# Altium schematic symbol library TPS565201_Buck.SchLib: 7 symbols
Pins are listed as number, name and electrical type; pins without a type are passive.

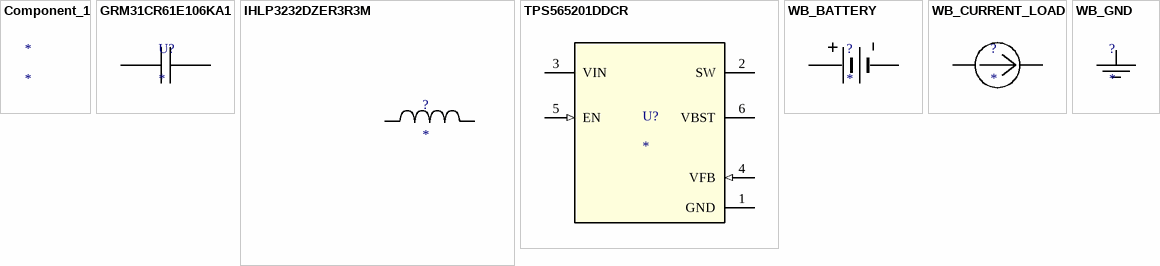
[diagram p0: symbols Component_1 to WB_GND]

## Component_1
designator *

## GRM31CR61E106KA1
designator U?
Imported; Manufacturer_Part_Number: GRM31CR61E106KA12L; Manufacturer_Name: MuRata; Cap_F: 0.00001; ESR_ohm: 0.004; VDC_V: 25; TYPE_2: TYPE
footprint 1206_190
pins: 1, 2

## IHLP3232DZER3R3M
designator ?
Imported; Manufacturer_Part_Number: IHLP3232DZER3R3M01; Manufacturer: Vishay; Vendor: Vishay-Dale; DESCRIPTION: Unknown; PACKAGE_DESIGNATOR: IHLP-3232DZ
footprint IHLP-3232DZ
pins: 1, 2

## TPS565201DDCR
designator U?
Imported; PartNumber: TPS565201DDCR; Manufacturer: Texas Instruments
footprint DDC0006A_N
pins: 1 GND (power), 2 SW (power), 3 VIN (power), 4 VFB (in), 5 EN (in), 6 VBST (power)

## WB_BATTERY
designator ?
Imported; Manufacturer_Part_Number: WB_BATTERY; PowerPortType: POWER_GROUND
pins: 1 +, 2 -

## WB_CURRENT_LOAD
designator ?
Imported; Manufacturer_Part_Number: WB_CURRENT_LOAD; PowerPortType: POWER_GROUND
pins: 1 +, 2 -

## WB_GND
designator ?
Imported; Manufacturer_Part_Number: WB_GND; PowerPortType: POWER_GROUND
pins: 1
